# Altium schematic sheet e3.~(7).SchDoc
size custom portrait; Address1: Address1; Address2: Address2; Address3: Address3; Address4: Address4; SheetNumber: 1; SheetTotal: 1; Scale: 1:1; Разраб.: Иванов; Обозначение документа: АБВГ.123456.001Э3; Пров.: Петров; Утв.: Сидоров; Наименование организации: ОАО "Ваша фирма"; Перв. применение: АБВГ.123456.000; Наименование изделия 1: Плата; Наименование изделия 2: Схема электрическая; Наименование изделия 3: принципиальная; Нач. отд.: Нач. отд.; Фамилия нач. отд.: Сидоров
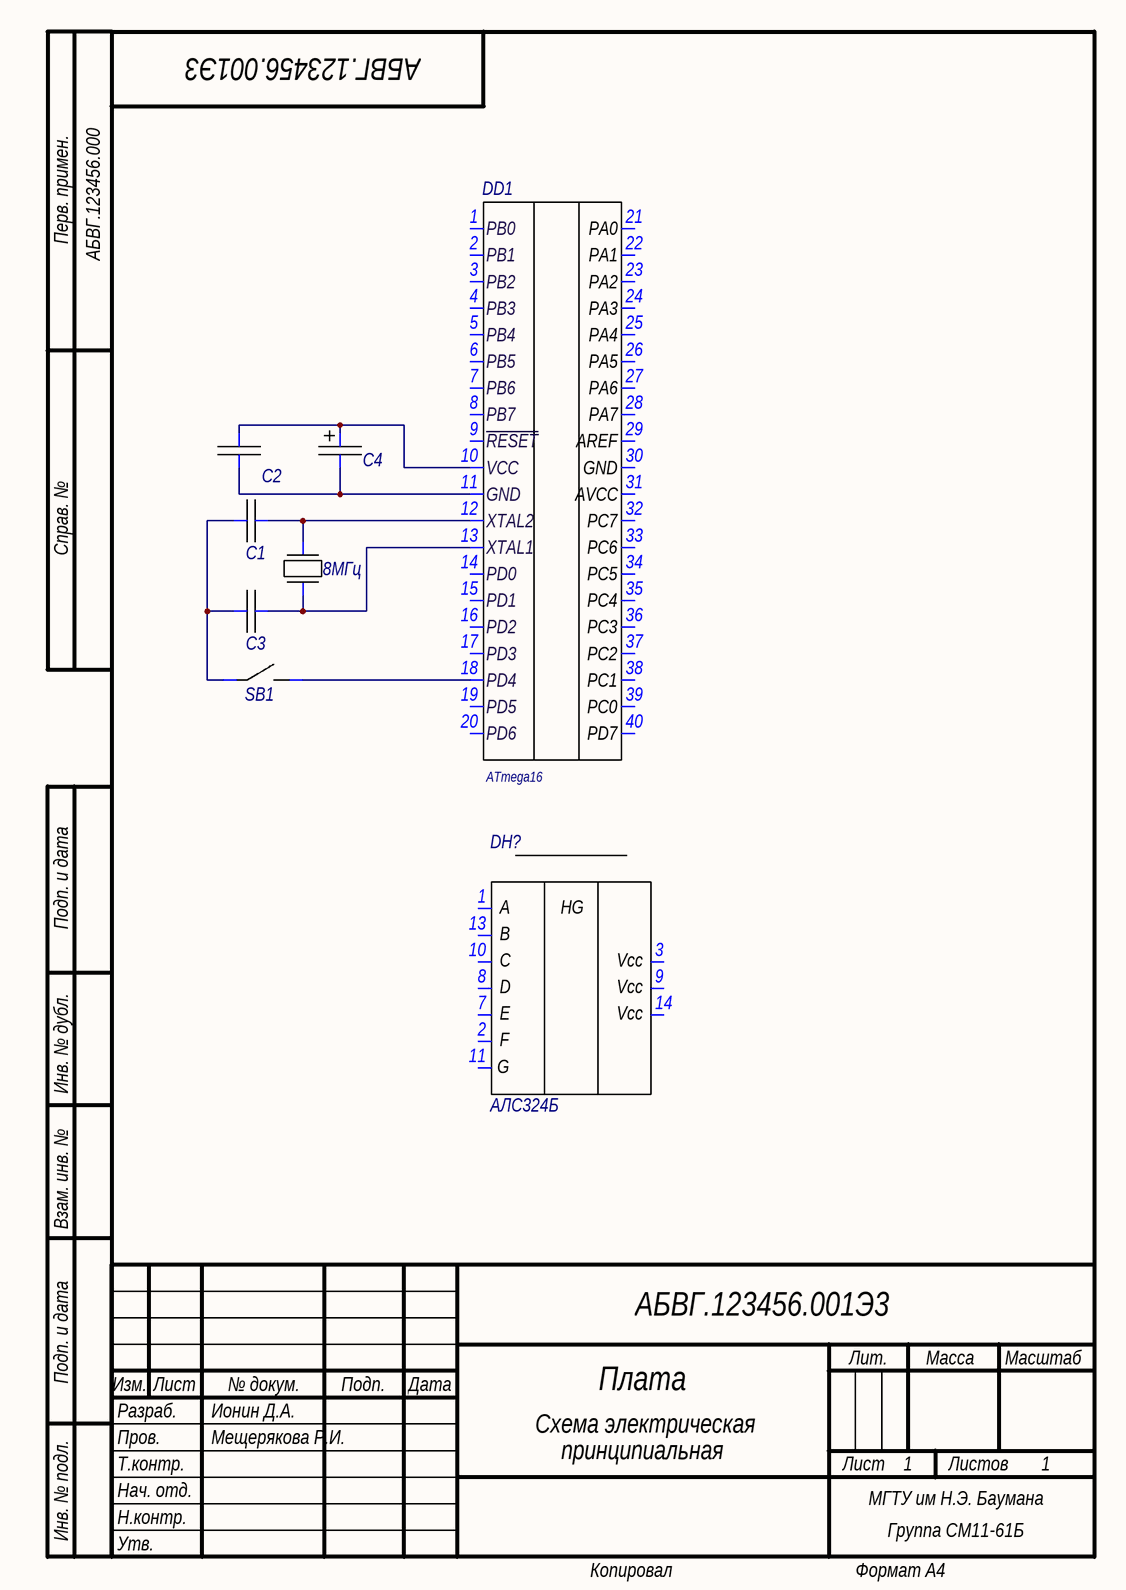
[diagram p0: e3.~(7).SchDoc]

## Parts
8МГц  8МГц
C1  Capacitor  (value not drawn)
C2  Capacitor  (value not drawn)
C3  Capacitor  (value not drawn)
C4  Capacitor +  (value not drawn)
DD1  ATmega16
DH?  АЛС324Б
SB1  Ключ  (value not drawn)

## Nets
Net8МГц_1: 8МГц.1 C3.2 DD1.13(XTAL1)
Net8МГц_2: 8МГц.2 C1.2 DD1.12(XTAL2)
NetC1_1: C1.1 C3.1 SB1.1
NetC2_1: C2.1 C4.1 DD1.11(GND)
NetC2_2: C2.2 C4.2 DD1.10(VCC)
NetDD1_18: DD1.18(PD4) SB1.2

Not connected (* = marked no-connect by the designer): DD1 1(PB0) 2(PB1) 3(PB2) 4(PB3) 5(PB4) 6(PB5) 7(PB6) 8(PB7) 9(~{RESET}) 14(PD0) 15(PD1) 16(PD2) 17(PD3) 19(PD5) 20(PD6) 21(PA0) 22(PA1) 23(PA2) 24(PA3) 25(PA4) 26(PA5) 27(PA6) 28(PA7) 29(AREF) 30(GND) 31(AVCC) 32(PC7) 33(PC6) 34(PC5) 35(PC4) 36(PC3) 37(PC2) 38(PC1) 39(PC0) 40(PD7); DH? 1 2 3 7 8 9 10 11 13 14

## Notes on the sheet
- Перв. примен.
- Справ. №
- Подп. и дата
- Инв. № дубл.
- Взам. инв. №
- Разраб.
- Изм.
- Лист
- Ионин Д.А.
- № докум.
- Подп.
- Дата
- Лит.
- Масса
- Масштаб
- Пров.
- Т.контр.
- Мещерякова Р.И.
- Листов
- Инв. № подл.
- Утв.
- Н.контр.
- МГТУ им Н.Э. Баумана
- Группа СМ11-61Б
- Копировал
- Формат А4

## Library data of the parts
8МГц = кварцевый резонатор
